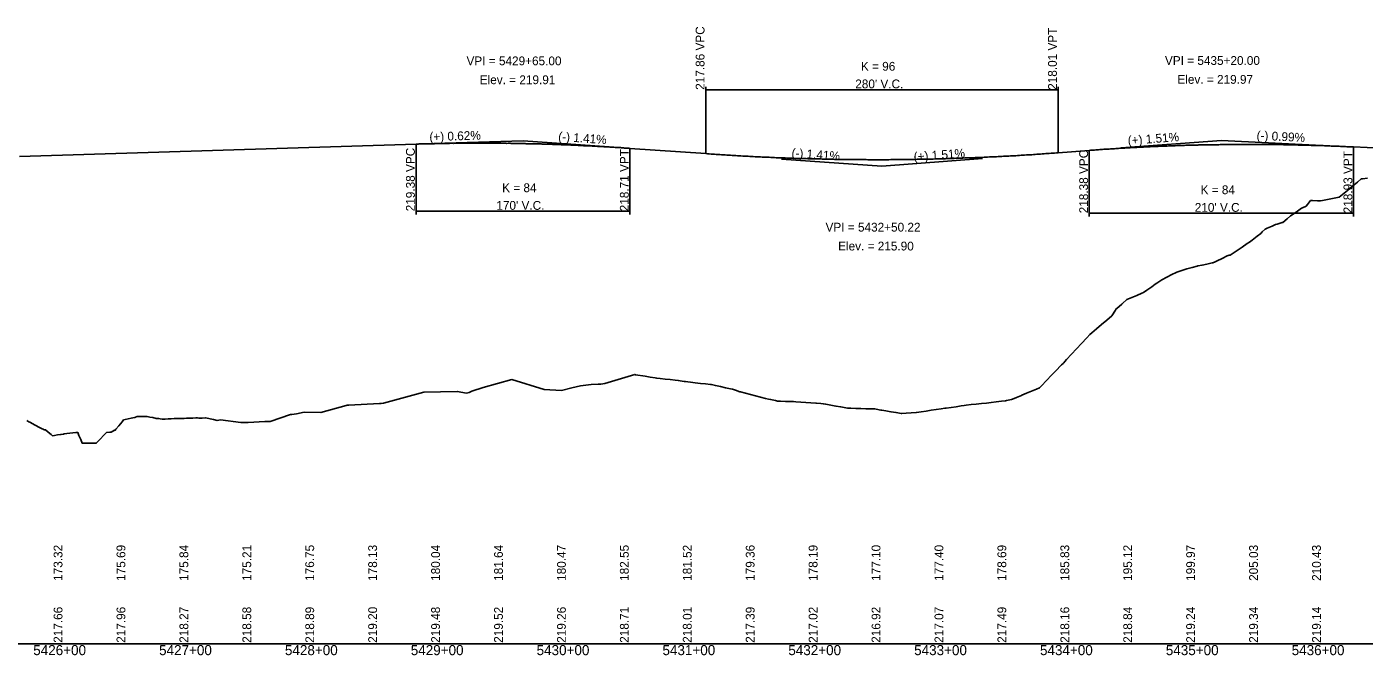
# Model space of a CAD drawing. Extents: x 1876258 to 1932803, y 754739 to 837911.
# Drawn here: x 1880552 to 1881615, y 775980 to 776479 of the extents above; entities that cross this region are included whole.
import ezdxf

# ---------------------------------------------------------------- set-up
doc = ezdxf.new("R2010")
doc.units = 0
for name, color, linetype in [('RD_DDB_GradeTX', 7, 'Continuous'), ('RD_DDB_Profile_EX', 7, 'Continuous'), ('RD_DDB_Profile_Lbl', 7, 'Continuous'), ('RD_DDB_Profile_PR', 7, 'Continuous'), ('RD_DDB_StaTX', 7, 'Continuous'), ('RD_DDB_StripGrade', 7, 'Continuous'), ('RD_DDB_VCLbl', 7, 'Continuous'), ('RD_GPK_Profile_Cell', 7, 'Continuous')]:
    doc.layers.add(name, color=color, linetype=linetype)

msp = doc.modelspace()

# ---------------------------------------------------------------- linework, layer by layer
at = {"layer": 'RD_DDB_GradeTX'}
for p, q in [((1880866.7, 776386.2), (1880946.6, 776388.7)), ((1881026.4, 776383.1), (1880946.6, 776388.7)), ((1881421.9, 776383), (1881501.6, 776389)), ((1881581.5, 776385), (1881501.6, 776389)), ((1881152, 776374.2), (1881231.8, 776368.6)), ((1881311.6, 776374.6), (1881231.8, 776368.6))]:
    msp.add_line(p, q, dxfattribs=at)
at = {"layer": 'RD_DDB_Profile_EX'}
for points in [[(1881373.8, 776210), (1881374.5, 776210.7), (1881375.7, 776211.9), (1881376.4, 776212.4), (1881377.1, 776213.4), (1881378.5, 776215), (1881382.5, 776219.3), (1881386.5, 776223.5), (1881390.5, 776227.8), (1881394.5, 776232.1), (1881396.9, 776234.8), (1881398.5, 776236.1), (1881402.4, 776239.4), (1881406.4, 776242.7), (1881410.4, 776246.1), (1881414.4, 776249.6), (1881417.4, 776254.1), (1881418, 776255.3), (1881418.4, 776255.6), (1881422.4, 776258.8), (1881423, 776259.4), (1881426.4, 776262.6), (1881430.4, 776264.2), (1881434.3, 776265.9), (1881438.3, 776267.6), (1881439.7, 776268.2), (1881442.3, 776270), (1881446.3, 776272.8), (1881448.9, 776274.7), (1881450.3, 776275.7), (1881453.4, 776277.8), (1881454.3, 776278.3), (1881458.3, 776280.3), (1881462.2, 776282.4), (1881465.7, 776284.2), (1881466.2, 776284.4), (1881469.2, 776285.4), (1881470.2, 776285.7), (1881474.2, 776286.9), (1881478.2, 776288), (1881482.2, 776289.1), (1881482.9, 776289.3), (1881486.2, 776290), (1881490.1, 776290.8), (1881494.1, 776291.7), (1881494.7, 776291.8), (1881495.4, 776292), (1881496, 776292.2), (1881498.1, 776293.3), (1881502.1, 776295.2), (1881506.1, 776297.2), (1881507.6, 776297.8), (1881508.6, 776297.9), (1881510.1, 776298.9), (1881514.1, 776301.6), (1881518, 776304.3), (1881522, 776307), (1881524, 776308.3), (1881526, 776309.9), (1881530, 776313), (1881532.8, 776315.2), (1881534, 776316.4), (1881536.4, 776318.5), (1881538, 776319.3), (1881542, 776321), (1881544.6, 776322.1), (1881546, 776322.5), (1881549.9, 776323.7), (1881550.4, 776323.8), (1881553.9, 776326.8), (1881556.5, 776329), (1881557.9, 776330), (1881561.9, 776332.9), (1881565.2, 776335.2), (1881565.9, 776335.5), (1881568.8, 776336.7), (1881569.9, 776338.1), (1881572.4, 776341.2), (1881573.9, 776341.2), (1881577.8, 776341.1), (1881580.4, 776341.1), (1881581.8, 776341.3), (1881585.8, 776342.1), (1881589.8, 776342.9), (1881593.8, 776343.7), (1881595.2, 776344), (1881597.8, 776346.1), (1881601.8, 776349.3), (1881605.7, 776352.6), (1881609.7, 776355.9), (1881612.6, 776358.4), (1881613.7, 776358.5), (1881617.7, 776359)], [(1880604.6, 776148.5), (1880605.4, 776148.5), (1880606, 776148.5), (1880607.5, 776148.5), (1880608.4, 776149.5), (1880610.9, 776152), (1880613.3, 776154.6), (1880615.7, 776157), (1880618.2, 776157.2), (1880619.2, 776157.2), (1880620.6, 776158.1), (1880622, 776158.9), (1880622.4, 776158.6), (1880623.1, 776159.5), (1880625.5, 776162.4), (1880628, 776165.4), (1880629.2, 776167), (1880630.4, 776167.3), (1880632.9, 776167.9), (1880635.3, 776168.4), (1880637.8, 776168.9), (1880638.2, 776169), (1880638.7, 776169.1), (1880639.9, 776169.8), (1880640.2, 776169.8), (1880642.6, 776169.8), (1880645.1, 776169.7), (1880647.5, 776169.7), (1880647.9, 776169.6), (1880650, 776169.2), (1880652.4, 776168.8), (1880655.1, 776168.2), (1880657.3, 776168), (1880658.3, 776167.8), (1880660.1, 776167.5), (1880662.2, 776167.7), (1880664.7, 776167.8), (1880667.1, 776167.9), (1880669.5, 776168.1), (1880672, 776168.2), (1880672.3, 776168.2), (1880674.4, 776168.2), (1880676.9, 776168.2), (1880677.4, 776168.2), (1880679.3, 776168.3), (1880681.8, 776168.4), (1880684.2, 776168.4), (1880686.7, 776168.5), (1880687.8, 776168.5), (1880689.1, 776168.4), (1880690.4, 776168.3), (1880691.6, 776168.4), (1880694, 776168.5), (1880694.4, 776168.5), (1880700.7, 776167.2), (1880703.5, 776166.4), (1880706.2, 776167), (1880722.4, 776165), (1880724.4, 776164.9), (1880728.3, 776165), (1880741.3, 776165.8), (1880745.6, 776165.6), (1880761.8, 776171.4), (1880763, 776171.4), (1880766.5, 776171.9), (1880772.8, 776173.1), (1880785.8, 776172.8), (1880806, 776178.5), (1880806.9, 776178.6), (1880807.5, 776178.7), (1880808.3, 776178.7), (1880832.5, 776179.9), (1880833.2, 776180), (1880833.6, 776180.1), (1880834, 776180.1), (1880835.7, 776180.4), (1880867.9, 776189), (1880894.3, 776189.6), (1880901.7, 776188.3), (1880903.9, 776188.8), (1880905.8, 776189.9), (1880914.9, 776192.7), (1880937.7, 776199), (1880963.3, 776191.2), (1880977.1, 776190.3), (1880985.5, 776192.5), (1880992.3, 776194.1), (1881000.8, 776195.1), (1881006.2, 776195.5), (1881008.3, 776195.5), (1881011.6, 776195.9), (1881035.5, 776203.1), (1881036, 776202.9), (1881043.7, 776201.6), (1881047.7, 776200.9), (1881051.7, 776200.3), (1881052.8, 776200.1), (1881055.6, 776199.8), (1881059.6, 776199.4), (1881063.6, 776199), (1881067.6, 776198.6)], [(1881067.6, 776198.6), (1881070, 776198.3), (1881071.6, 776198), (1881074.7, 776197.4), (1881075.6, 776197.4), (1881077.6, 776197.2), (1881079.6, 776197), (1881083.5, 776196.5), (1881087.5, 776196), (1881091.5, 776195.6), (1881095.5, 776195.1), (1881096.5, 776195), (1881099.5, 776194.3), (1881103.5, 776193.4), (1881107.5, 776192.5), (1881111.5, 776191.6), (1881113, 776191.3), (1881115.4, 776190.5), (1881118.9, 776189.4), (1881119.4, 776189.2), (1881123.4, 776188.1), (1881127.4, 776187.1), (1881131.4, 776186), (1881135.4, 776185.1), (1881139.4, 776184.1), (1881141.6, 776183.5), (1881143.3, 776183.2), (1881147.3, 776182.3), (1881148.9, 776181.9), (1881151.3, 776181.9), (1881155.3, 776181.7), (1881159.3, 776181.6), (1881161.5, 776181.5), (1881163.3, 776181.4), (1881167.3, 776181.1), (1881171.2, 776180.8), (1881175.2, 776180.5), (1881179.2, 776180.3), (1881179.9, 776180.2), (1881183.2, 776180), (1881185.2, 776179.8), (1881187.2, 776179.4), (1881191.2, 776178.7), (1881195.2, 776178), (1881199.1, 776177.3), (1881203.1, 776176.6), (1881204.6, 776176.3), (1881207.1, 776176.3), (1881211.1, 776176.1), (1881215.1, 776176), (1881219.1, 776175.9), (1881222, 776175.8), (1881223.1, 776175.8), (1881226.1, 776175.8), (1881227.1, 776175.6), (1881231, 776174.8), (1881231.7, 776174.7), (1881235, 776174.1), (1881239, 776173.5), (1881243, 776172.8), (1881247, 776172.2), (1881247.5, 776172.1), (1881251, 776172.3), (1881255, 776172.6), (1881258.9, 776172.8), (1881259.3, 776172.9), (1881262.9, 776173.4), (1881266.9, 776174), (1881270.9, 776174.6), (1881274.9, 776175.2), (1881278.9, 776175.8), (1881281.7, 776176.2), (1881282.9, 776176.3), (1881286.8, 776176.9), (1881290.8, 776177.5), (1881294.8, 776178.1), (1881297.1, 776178.4), (1881298.8, 776178.6), (1881302.8, 776179.1), (1881306.8, 776179.5), (1881310.8, 776180), (1881314.8, 776180.4), (1881318.7, 776180.9), (1881322.7, 776181.3), (1881326.7, 776181.8), (1881330.1, 776182.2), (1881330.7, 776182.3), (1881334.7, 776183.3), (1881335.5, 776183.5), (1881338.7, 776184.8), (1881342.7, 776186.4), (1881343, 776186.6), (1881346.6, 776188.1), (1881350.6, 776189.7), (1881354.6, 776191.4), (1881357, 776192.4), (1881358.6, 776194.1), (1881362.6, 776198.3), (1881366.6, 776202.4), (1881370.6, 776206.6), (1881373.8, 776210)], [(1880552.2, 776166.4), (1880553.9, 776165.5), (1880554.6, 776165.1), (1880557.1, 776163.8), (1880558.4, 776163.1), (1880559.5, 776162.5), (1880561.9, 776161.2), (1880564.4, 776159.9), (1880565.3, 776159.5), (1880566.2, 776159.2), (1880566.8, 776159.1), (1880567.2, 776159.1), (1880569.3, 776157.3), (1880571.7, 776155.3), (1880572.8, 776154.4), (1880574.2, 776154.6), (1880576.6, 776155), (1880579.1, 776155.3), (1880579.6, 776155.4), (1880581.5, 776155.7), (1880581.9, 776155.8), (1880584, 776156.1), (1880586.4, 776156.4), (1880588.8, 776156.6), (1880591.3, 776156.9), (1880592.7, 776157.1), (1880593.7, 776154.6), (1880595.1, 776151.3), (1880596.3, 776148.5), (1880596.8, 776148.5), (1880598.9, 776148.5), (1880601.1, 776148.5), (1880601.7, 776148.5), (1880602.3, 776148.5), (1880603.5, 776148.5), (1880604.6, 776148.5)]]:
    msp.add_lwpolyline(points, dxfattribs=at)
at = {"layer": 'RD_DDB_Profile_PR'}
for p, q in [((1880546.6, 776376.3), (1880861.6, 776386.1)), ((1881031.6, 776382.7), (1881091.8, 776378.5)), ((1881371.8, 776379.2), (1881396.6, 776381.1)), ((1881606.6, 776383.8), (1882421.6, 776343.6))]:
    msp.add_line(p, q, dxfattribs=at)
for points in [[(1880861.6, 776386.1), (1880865, 776386.2), (1880868.4, 776386.2), (1880871.8, 776386.3), (1880875.2, 776386.4), (1880878.6, 776386.5), (1880882, 776386.6), (1880885.4, 776386.6), (1880888.8, 776386.7), (1880892.2, 776386.7), (1880895.6, 776386.8), (1880899, 776386.8), (1880902.4, 776386.8), (1880905.8, 776386.8), (1880909.2, 776386.8), (1880912.6, 776386.8), (1880916, 776386.8), (1880919.4, 776386.8), (1880922.8, 776386.8), (1880926.2, 776386.8), (1880929.6, 776386.8), (1880933, 776386.7), (1880936.4, 776386.7), (1880939.8, 776386.6), (1880943.2, 776386.6), (1880946.6, 776386.5), (1880950, 776386.4), (1880953.4, 776386.4), (1880956.8, 776386.3), (1880960.2, 776386.2), (1880963.6, 776386.1), (1880967, 776386), (1880970.4, 776385.9), (1880973.8, 776385.8), (1880977.2, 776385.6), (1880980.6, 776385.5), (1880984, 776385.4), (1880987.4, 776385.2), (1880990.8, 776385.1), (1880994.2, 776384.9), (1880997.6, 776384.7), (1881001, 776384.6), (1881004.4, 776384.4), (1881007.8, 776384.2), (1881011.2, 776384), (1881014.6, 776383.8), (1881018, 776383.6), (1881021.4, 776383.4), (1881024.8, 776383.2), (1881028.2, 776382.9), (1881031.6, 776382.7)], [(1881396.6, 776381.1), (1881400.8, 776381.4), (1881405, 776381.7), (1881409.2, 776382), (1881413.4, 776382.2), (1881417.6, 776382.5), (1881421.8, 776382.8), (1881426, 776383), (1881430.2, 776383.3), (1881434.4, 776383.5), (1881438.6, 776383.7), (1881442.8, 776383.9), (1881447, 776384.1), (1881451.2, 776384.3), (1881455.4, 776384.5), (1881459.6, 776384.6), (1881463.8, 776384.8), (1881468, 776384.9), (1881472.2, 776385.1), (1881476.4, 776385.2), (1881480.6, 776385.3), (1881484.8, 776385.4), (1881489, 776385.5), (1881493.2, 776385.6), (1881497.4, 776385.6), (1881501.6, 776385.7), (1881505.8, 776385.8), (1881510, 776385.8), (1881514.2, 776385.8), (1881518.4, 776385.8), (1881522.6, 776385.8), (1881526.8, 776385.8), (1881531, 776385.8), (1881535.2, 776385.8), (1881539.4, 776385.8), (1881543.6, 776385.7), (1881547.8, 776385.7), (1881552, 776385.6), (1881556.2, 776385.5), (1881560.4, 776385.4), (1881564.6, 776385.3), (1881568.8, 776385.2), (1881573, 776385.1), (1881577.2, 776385), (1881581.4, 776384.9), (1881585.6, 776384.7), (1881589.8, 776384.5), (1881594, 776384.4), (1881598.2, 776384.2), (1881602.4, 776384), (1881606.6, 776383.8)], [(1881091.8, 776378.5), (1881097.4, 776378.1), (1881103, 776377.7), (1881108.6, 776377.4), (1881114.2, 776377), (1881119.8, 776376.7), (1881125.4, 776376.4), (1881131, 776376.1), (1881136.6, 776375.8), (1881142.2, 776375.6), (1881147.8, 776375.3), (1881153.4, 776375.1), (1881159, 776374.9), (1881164.6, 776374.7), (1881170.2, 776374.6), (1881175.8, 776374.4), (1881181.4, 776374.3), (1881187, 776374.1), (1881192.6, 776374), (1881198.2, 776373.9), (1881203.8, 776373.9), (1881209.4, 776373.8), (1881215, 776373.8), (1881220.6, 776373.7), (1881226.2, 776373.7), (1881231.8, 776373.7), (1881237.4, 776373.7), (1881243, 776373.8), (1881248.6, 776373.8), (1881254.2, 776373.9), (1881259.8, 776374), (1881265.4, 776374.1), (1881271, 776374.2), (1881276.6, 776374.4), (1881282.2, 776374.5), (1881287.8, 776374.7), (1881293.4, 776374.9), (1881299, 776375.1), (1881304.6, 776375.3), (1881310.2, 776375.5), (1881315.8, 776375.8), (1881321.4, 776376), (1881327, 776376.3), (1881332.6, 776376.6), (1881338.2, 776376.9), (1881343.8, 776377.3), (1881349.4, 776377.6), (1881355, 776378), (1881360.6, 776378.4), (1881366.2, 776378.8), (1881371.8, 776379.2)]]:
    msp.add_spline(points, degree=3, dxfattribs=at)
at = {"layer": 'RD_DDB_VCLbl'}
for p, q in [((1881091.8, 776431.7), (1881091.8, 776378.5)), ((1881091.8, 776429.2), (1881371.8, 776429.2)), ((1881371.8, 776431.7), (1881371.8, 776379.2)), ((1880861.6, 776330.2), (1880861.6, 776386.1)), ((1881031.6, 776330.2), (1881031.6, 776382.7)), ((1881396.6, 776328.6), (1881396.6, 776381.1)), ((1881606.6, 776328.6), (1881606.6, 776383.8)), ((1880861.6, 776332.7), (1881031.6, 776332.7)), ((1881396.6, 776331.1), (1881606.6, 776331.1))]:
    msp.add_line(p, q, dxfattribs=at)
at = {"layer": 'RD_GPK_Profile_Cell'}
msp.add_line((1877681.6, 775989.1), (1883481.6, 775989.1), dxfattribs=at)

# ---------------------------------------------------------------- texts
at = {"layer": 'RD_DDB_GradeTX'}
for s, rotation, p in [('(+) 0.62%', 1.7643, (1880872.3, 776388.4)), ('(-) 1.41%', 355.9797, (1880974.4, 776388.7)), ('(+) 1.51%', 4.3149, (1881427.4, 776385.4)), ('(-) 0.99%', 357.1773, (1881529.4, 776389.6)), ('(-) 1.41%', 355.9797, (1881159.8, 776375.7)), ('(+) 1.51%', 4.3149, (1881257.3, 776372.5))]:
    msp.add_text(s, height=7, rotation=rotation, dxfattribs=at).set_placement(p)
at = {"layer": 'RD_DDB_Profile_Lbl'}
for s, p in [('VPI = 5429+65.00', (1880901.7, 776448.7)), ('VPI = 5435+20.00', (1881456.7, 776449)), ('Elev. = 219.91', (1880912.2, 776433.7)), ('Elev. = 219.97', (1881466.6, 776434)), ('VPI = 5432+50.22', (1881187, 776316.6)), ('Elev. = 215.90', (1881197, 776301.6))]:
    msp.add_text(s, height=7, dxfattribs=at).set_placement(p)
at = {"layer": 'RD_DDB_StaTX'}
for s, p in [('5426+00', (1880557.4, 775980.1)), ('5427+00', (1880657.4, 775980.1)), ('5428+00', (1880757.4, 775980.1)), ('5429+00', (1880857.4, 775980.1)), ('5430+00', (1880957.4, 775980.1)), ('5431+00', (1881057.4, 775980.1)), ('5432+00', (1881157.4, 775980.1)), ('5433+00', (1881257.4, 775980.1)), ('5434+00', (1881357.4, 775980.1)), ('5435+00', (1881457.4, 775980.1)), ('5436+00', (1881557.4, 775980.1))]:
    msp.add_text(s, height=8, dxfattribs=at).set_placement(p)
at = {"layer": 'RD_DDB_StripGrade'}
for s, p in [('217.86 VPC', (1881090.8, 776429.2)), ('218.01 VPT', (1881370.8, 776429.2)), ('219.38 VPC', (1880860.6, 776332.7)), ('218.71 VPT', (1881030.6, 776332.7)), ('218.38 VPC', (1881395.6, 776331.1)), ('218.93 VPT', (1881605.6, 776331.1)), ('173.32', (1880580.6, 776039.1)), ('175.69', (1880630.6, 776039.1)), ('175.84', (1880680.6, 776039.1)), ('175.21', (1880730.6, 776039.1)), ('176.75', (1880780.6, 776039.1)), ('178.13', (1880830.6, 776039.1)), ('180.04', (1880880.6, 776039.1)), ('181.64', (1880930.6, 776039.1)), ('180.47', (1880980.6, 776039.1)), ('182.55', (1881030.6, 776039.1)), ('181.52', (1881080.6, 776039.1)), ('179.36', (1881130.6, 776039.1)), ('178.19', (1881180.6, 776039.1)), ('177.10', (1881230.6, 776039.1)), ('177.40', (1881280.6, 776039.1)), ('178.69', (1881330.6, 776039.1)), ('185.83', (1881380.6, 776039.1)), ('195.12', (1881430.6, 776039.1)), ('199.97', (1881480.6, 776039.1)), ('205.03', (1881530.6, 776039.1)), ('210.43', (1881580.6, 776039.1)), ('217.66', (1880580.6, 775989.9)), ('217.96', (1880630.6, 775989.9)), ('218.27', (1880680.6, 775989.9)), ('218.58', (1880730.6, 775989.9)), ('218.89', (1880780.6, 775989.9)), ('219.20', (1880830.6, 775989.9)), ('219.48', (1880880.6, 775989.9)), ('219.52', (1880930.6, 775989.9)), ('219.26', (1880980.6, 775989.9)), ('218.71', (1881030.6, 775989.9)), ('218.01', (1881080.6, 775989.9)), ('217.39', (1881130.6, 775989.9)), ('217.02', (1881180.6, 775989.9)), ('216.92', (1881230.6, 775989.9)), ('217.07', (1881280.6, 775989.9)), ('217.49', (1881330.6, 775989.9)), ('218.16', (1881380.6, 775989.9)), ('218.84', (1881430.6, 775989.9)), ('219.24', (1881480.6, 775989.9)), ('219.34', (1881530.6, 775989.9)), ('219.14', (1881580.6, 775989.9))]:
    msp.add_text(s, height=7, rotation=90, dxfattribs=at).set_placement(p)
at = {"layer": 'RD_DDB_VCLbl'}
for s, p in [('K = 96', (1881215.1, 776444.4)), ("280' V.C.", (1881210.6, 776430.4)), ('K = 84', (1880930, 776347.9)), ('K = 84', (1881485, 776346.3)), ("170' V.C.", (1880925.4, 776333.9)), ("210' V.C.", (1881480.4, 776332.3))]:
    msp.add_text(s, height=7, dxfattribs=at).set_placement(p)

doc.saveas('drawing.dxf')
